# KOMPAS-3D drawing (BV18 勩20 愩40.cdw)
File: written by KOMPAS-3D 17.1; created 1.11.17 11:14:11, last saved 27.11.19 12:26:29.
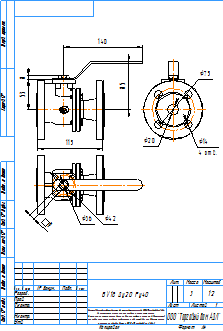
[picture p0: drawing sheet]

Sheet 1: A4, portrait

Title block, sheet 1: name: BV18 Ду20 Ру40; material: Сталь 10  ГОСТ 1050-88; mass: 3; sheets: 1; sheet format: A4; stored path: C:\Users\kka\KOMPAS_Work\!Trash\BV18\KOMPAS 2D\BV18 Ду50 Ру40.cdw

Views: Проекционный вид 4, Проекционный вид 5
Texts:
  kka
  adl
  Рама для чертежей
  Лит-Масса-Масштаб
  Материал-Предприятие
  Масштаб
  Изм.
  Лист
  № докум.
  Подп.
  Дата
  Лит.
  Разраб.
  Пров.
  Т.контр.
  Листов
  Внимание! Данный продукт является объектом авторского права ООО «Торговый Дом АДЛ».
  Запрещается изменение, копирование, распространение
  (в том числе путем копирования на другие сайты и ресурсы в Интернете)
  или любое иное использование информации и объектов без предварительного
  согласия правообладателя (ООО «Торговый Дом АДЛ»).
  Н.контр.
  Утв.
  ООО "Торговый дом АДЛ"
  Изменение
  Номер документа
  Подпись
  Обозначение документа
  Наименование изделия
  Масса изделия по ГОСТ 2.109-73
  Порядковый номер листа
  Общее количество листов в документе
  Характер работы, выполненной лицом, подписавшим документ
  Наименование или индекс предприятия, выпускающего документ
  Инв. № подл.
  Подп. и дата
  Взам. инв. №
  Инв. № дубл.
  Инвентарный номер подлинника по ГОСТ 2.501-68
  Подпись принявшего подлинник в отдел технической документации
  Инвентарный номер подлинника, взамен которого выпущен данный подлинник
  Инвентарный номер дубликата по ГОСТ 2.502-68
  Подпись принявшего дубликат в отдел технической документации
  Справ. №
  Перв. примен.
  Обозначение документа, взамен или на основании которого выпущен данный документ
  Обозначение документа, в котором впервые записан данный документ
  Подпись лица, копировавшего чертеж
  Обозначение формата листа
  !Рама для чертежа
Dimensions and other numbers on the sheet: 115; 140; 85; 53; 8; 75; 14; 4 отв.; 20; 1:2; 1; 3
